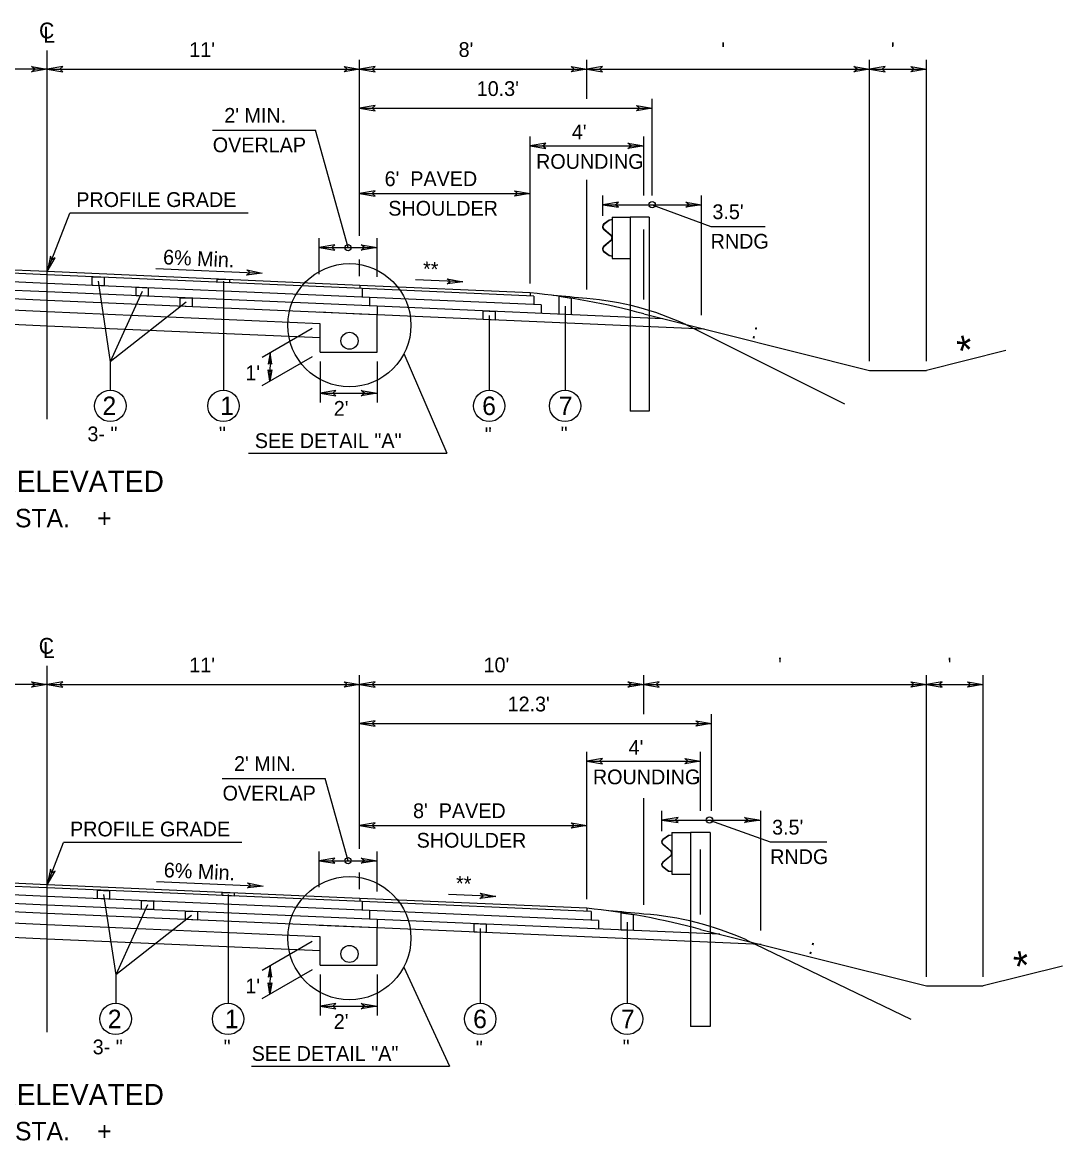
# Model space of a CAD drawing. Extents: x -592 to 1199, y -590 to 416.
# Drawn here: x 814.1 to 912.8, y 44 to 150 of the extents above; entities that cross this region are included whole.
import ezdxf

# ---------------------------------------------------------------- set-up
doc = ezdxf.new("R2010")
doc.units = 0
doc.layers.add('1', color=7, linetype='Continuous')
doc.layers.add('Des_ Drain_ Ftrs', color=7, linetype='Continuous')

msp = doc.modelspace()

# ---------------------------------------------------------------- linework, layer by layer
at = {"layer": '1'}
for p, q in [((816.45, 112.39), (816.45, 147.34)), ((846.08, 129.78), (846.08, 146.46)), ((867.64, 142.76), (867.64, 146.46)), ((894.46, 117.88), (894.46, 146.46)), ((899.85, 117.88), (899.85, 146.46)), ((816.45, 145.58), (786.81, 145.58)), ((816.45, 145.58), (846.08, 145.58)), ((846.08, 145.58), (867.64, 145.58)), ((867.64, 145.58), (894.46, 145.58)), ((894.46, 145.58), (899.85, 145.58)), ((873.83, 133.6), (873.83, 142.76)), ((846.08, 141.88), (873.83, 141.88)), ((832.11, 139.79), (841.88, 139.79)), ((844.98, 128.65), (841.88, 139.79)), ((862.25, 125.25), (862.25, 139.18)), ((873.03, 133.6), (873.03, 139.18)), ((862.25, 138.3), (873.03, 138.3)), ((867.64, 124.69), (867.64, 135.07)), ((846.08, 133.78), (862.25, 133.78)), ((869.14, 131.65), (869.14, 133.6)), ((869.14, 132.72), (878.52, 132.72)), ((873.83, 132.72), (879.39, 130.65)), ((878.52, 122.24), (878.52, 133.6)), ((816.45, 126.37), (818.59, 131.91)), ((835.5, 131.91), (818.59, 131.91)), ((870.05, 131.54), (870.05, 127.6)), ((870.05, 131.54), (871.74, 131.54)), ((871.74, 131.54), (871.74, 113.14)), ((873.56, 131.54), (871.74, 131.54)), ((873.56, 131.54), (873.56, 113.14)), ((869.74, 131.25), (869.22, 130.86)), ((869.22, 130.45), (869.95, 129.82)), ((869.75, 131.22), (869.24, 130.84)), ((870.05, 131.31), (869.74, 131.25)), ((870.05, 131.28), (869.75, 131.22)), ((879.39, 130.65), (884.54, 130.65)), ((842.24, 126.12), (842.24, 129.53)), ((847.73, 125.88), (847.73, 129.53)), ((869.2, 130.43), (869.94, 129.8)), ((870.02, 129.61), (870.02, 129.53)), ((870.05, 129.61), (870.05, 129.53)), ((873.03, 123.72), (873.03, 130.37)), ((842.24, 128.65), (847.73, 128.65)), ((869.94, 129.35), (869.2, 128.71)), ((869.95, 129.32), (869.22, 128.69)), ((816.45, 126.07), (786.47, 127.38)), ((816.45, 126.37), (786.81, 127.66)), ((846.08, 125.95), (846.08, 127.52)), ((869.22, 128.28), (869.74, 127.89)), ((869.24, 128.3), (869.75, 127.92)), ((869.74, 127.89), (870.05, 127.83)), ((869.75, 127.92), (870.05, 127.86)), ((870.05, 127.6), (871.74, 127.6)), ((816.45, 125.26), (785.55, 126.61)), ((846.09, 125.07), (816.45, 126.37)), ((826.74, 126.67), (836.85, 126.23)), ((816.45, 124.45), (784.62, 125.84)), ((846.32, 124.76), (816.45, 126.07)), ((847.03, 123.92), (816.45, 125.26)), ((821.27, 125.45), (822.43, 117.83)), ((833.16, 125.46), (833.16, 115.13)), ((855.86, 125.39), (851.37, 125.59)), ((816.45, 123.64), (784.62, 125.03)), ((847.73, 123.08), (816.45, 124.45)), ((825.45, 124.47), (822.43, 117.83)), ((862.25, 124.37), (846.09, 125.07)), ((846.09, 125.07), (846.09, 124.77)), ((862.61, 124.05), (846.32, 124.76)), ((846.32, 124.76), (846.32, 123.95)), ((862.25, 124.37), (862.25, 124.07)), ((816.45, 122.56), (790.01, 123.72)), ((847.73, 122.27), (816.45, 123.64)), ((829.62, 123.46), (822.43, 117.83)), ((863.31, 123.21), (847.03, 123.92)), ((847.03, 123.92), (847.03, 123.11)), ((847.73, 123.08), (847.73, 122.27)), ((874.86, 121.9), (847.73, 123.08)), ((862.61, 124.05), (862.61, 123.25)), ((863.31, 123.21), (863.31, 122.41)), ((865.57, 123.1), (865.57, 115.13)), ((869.14, 123.59), (869.14, 123.59)), ((816.45, 121.21), (790.01, 122.37)), ((842.34, 121.43), (816.45, 122.56)), ((846.08, 122.35), (842.25, 122.51)), ((847.73, 122.27), (846.09, 122.35)), ((847.73, 118.74), (847.73, 122.27)), ((878.78, 120.92), (847.73, 122.27)), ((858.37, 122.22), (858.37, 115.13)), ((873.03, 122.36), (894.46, 117)), ((842.34, 120.08), (816.45, 121.21)), ((841.58, 120.99), (836.82, 118.24)), ((842.34, 118.74), (842.34, 121.43)), ((842.34, 121.43), (842.34, 121.43)), ((877.02, 121.36), (892.07, 113.83)), ((907.38, 118.88), (899.85, 117)), ((822.43, 117.83), (822.43, 115.13)), ((841.58, 118.3), (836.81, 115.54)), ((837.59, 118.68), (837.57, 115.98)), ((842.34, 118.74), (847.73, 118.74)), ((842.34, 117.86), (842.34, 113.97)), ((847.73, 117.86), (847.73, 113.97)), ((850.29, 118.6), (854.34, 109.14)), ((894.46, 117), (899.85, 117)), ((842.34, 114.85), (847.73, 114.85)), ((873.56, 113.14), (871.74, 113.14)), ((835.55, 109.14), (854.34, 109.14)), ((816.45, 54.25), (816.45, 88.97)), ((846.08, 71.63), (846.08, 88.09)), ((873.03, 84.39), (873.03, 88.09)), ((899.85, 59.5), (899.85, 88.09)), ((905.24, 59.5), (905.24, 88.09)), ((816.45, 87.21), (786.81, 87.21)), ((816.45, 87.21), (846.08, 87.21)), ((846.08, 87.21), (873.03, 87.21)), ((873.03, 87.21), (899.85, 87.21)), ((899.85, 87.21), (905.24, 87.21)), ((879.45, 75.24), (879.45, 84.39)), ((846.08, 83.51), (879.45, 83.51)), ((867.64, 66.87), (867.64, 80.82)), ((878.41, 75.24), (878.41, 80.82)), ((867.64, 79.94), (878.41, 79.94)), ((833.04, 78.31), (842.81, 78.31)), ((844.98, 70.5), (842.81, 78.31)), ((873.03, 66.33), (873.03, 76.43)), ((874.76, 73.29), (874.76, 75.24)), ((874.76, 74.36), (884.15, 74.36)), ((879.28, 74.36), (885.04, 72.28)), ((884.15, 63.87), (884.15, 75.24)), ((846.08, 73.84), (867.64, 73.84)), ((816.45, 68.22), (817.99, 72.23)), ((834.91, 72.23), (817.99, 72.23)), ((875.38, 72.89), (874.85, 72.5)), ((875.39, 72.86), (874.86, 72.48)), ((875.71, 72.94), (875.38, 72.89)), ((875.71, 72.91), (875.39, 72.86)), ((875.71, 73.17), (875.71, 69.24)), ((875.71, 73.17), (877.46, 73.17)), ((877.46, 73.17), (877.46, 54.78)), ((879.35, 73.17), (877.46, 73.17)), ((879.35, 73.17), (879.35, 54.78)), ((885.04, 72.28), (890.39, 72.28)), ((842.24, 67.98), (842.24, 71.38)), ((847.73, 67.59), (847.73, 71.38)), ((874.83, 72.07), (875.59, 71.43)), ((874.85, 72.09), (875.61, 71.45)), ((875.68, 71.24), (875.68, 71.17)), ((875.71, 71.24), (875.71, 71.17)), ((878.41, 65.41), (878.41, 71.56)), ((842.24, 70.5), (847.73, 70.5)), ((875.59, 70.98), (874.83, 70.35)), ((875.61, 70.96), (874.85, 70.32)), ((816.45, 67.92), (786.47, 69.23)), ((816.45, 68.22), (786.81, 69.52)), ((846.08, 67.81), (846.08, 69.38)), ((874.85, 69.91), (875.38, 69.52)), ((874.86, 69.94), (875.39, 69.55)), ((875.38, 69.52), (875.71, 69.47)), ((875.39, 69.55), (875.71, 69.5)), ((875.71, 69.24), (877.46, 69.24)), ((816.45, 67.11), (785.55, 68.46)), ((846.09, 66.93), (816.45, 68.22)), ((846.32, 66.62), (816.45, 67.92)), ((826.81, 68.54), (836.92, 68.1)), ((816.45, 66.3), (784.62, 67.69)), ((816.45, 65.5), (784.62, 66.88)), ((847.03, 65.78), (816.45, 67.11)), ((821.78, 67.29), (822.94, 59.67)), ((833.6, 67.31), (833.6, 56.98)), ((867.64, 65.99), (846.09, 66.93)), ((846.09, 66.93), (846.09, 66.63)), ((859, 67.11), (854.5, 67.31)), ((847.73, 64.94), (816.45, 66.3)), ((825.95, 66.31), (822.94, 59.67)), ((868.04, 65.67), (846.32, 66.62)), ((846.32, 66.62), (846.32, 65.81)), ((868.73, 64.83), (847.03, 65.78)), ((847.03, 65.78), (847.03, 64.97)), ((867.64, 65.99), (867.64, 65.69)), ((816.45, 64.42), (790.01, 65.57)), ((847.73, 64.13), (816.45, 65.5)), ((830.13, 65.3), (822.94, 59.67)), ((847.73, 64.94), (847.73, 64.13)), ((880.25, 63.52), (847.73, 64.94)), ((868.04, 65.67), (868.04, 64.86)), ((868.73, 64.83), (868.73, 64.02)), ((874.76, 65.23), (874.76, 65.23)), ((816.45, 63.07), (790.01, 64.22)), ((842.34, 63.29), (816.45, 64.42)), ((846.08, 64.2), (842.25, 64.37)), ((847.73, 64.13), (846.09, 64.2)), ((847.73, 60.59), (847.73, 64.13)), ((884.17, 62.54), (847.73, 64.13)), ((857.52, 64.06), (857.52, 56.98)), ((871.46, 64.67), (871.46, 56.98)), ((878.41, 63.98), (899.85, 58.62)), ((842.34, 61.94), (816.45, 63.07)), ((841.58, 62.85), (836.82, 60.1)), ((842.34, 60.59), (842.34, 63.29)), ((842.34, 63.29), (842.34, 63.29)), ((882.76, 62.99), (898.38, 55.47)), ((837.59, 60.54), (837.57, 57.83)), ((842.34, 60.59), (847.73, 60.59)), ((912.77, 60.5), (905.24, 58.62)), ((822.94, 59.67), (822.94, 56.98)), ((841.58, 60.15), (836.81, 57.4)), ((842.34, 59.71), (842.34, 55.83)), ((847.73, 59.71), (847.73, 55.83)), ((850.26, 60.41), (854.62, 51.02)), ((899.85, 58.62), (905.24, 58.62)), ((842.34, 56.71), (847.73, 56.71)), ((879.35, 54.78), (877.46, 54.78)), ((835.83, 51.02), (854.62, 51.02))]:
    msp.add_line(p, q, dxfattribs=at)
for points in [[(820.7, 125.88), (821.84, 125.83), (821.84, 125.02), (820.7, 125.07)], [(832.58, 125.66), (833.73, 125.61), (833.73, 125.31), (832.58, 125.36)], [(824.87, 124.89), (826.02, 124.84), (826.02, 124.03), (824.87, 124.08)], [(829.05, 123.9), (830.19, 123.85), (830.19, 123.04), (829.05, 123.09)], [(865, 124.03), (866.14, 123.85), (866.14, 122.28), (865, 122.33)], [(857.8, 122.64), (858.95, 122.59), (858.95, 121.78), (857.8, 121.83)], [(821.2, 67.71), (822.35, 67.66), (822.35, 66.86), (821.2, 66.91)], [(833.03, 67.5), (834.18, 67.45), (834.18, 67.15), (833.03, 67.2)], [(825.38, 66.72), (826.53, 66.67), (826.53, 65.86), (825.38, 65.91)], [(830.7, 65.68), (830.7, 64.87), (829.55, 64.92), (829.55, 65.73)], [(870.88, 65.57), (872.03, 65.39), (872.03, 63.88), (870.88, 63.93)], [(856.95, 64.54), (858.09, 64.49), (858.09, 63.68), (856.95, 63.73)]]:
    msp.add_lwpolyline(points, close=True, dxfattribs=at)
for centre, radius in [((873.83, 132.72), 0.3), ((844.98, 128.65), 0.3), ((845.11, 121.29), 5.84), ((845.12, 119.81), 0.808), ((822.43, 113.64), 1.49), ((833.16, 113.64), 1.49), ((858.37, 113.64), 1.49), ((865.57, 113.64), 1.49), ((844.98, 70.5), 0.3), ((845.11, 63.15), 5.84), ((845.12, 61.66), 0.808), ((822.94, 55.5), 1.49), ((833.6, 55.5), 1.49), ((857.52, 55.5), 1.49), ((871.46, 55.5), 1.49)]:
    msp.add_circle(centre, radius, dxfattribs=at)
for centre, radius, start, end in [((869.39, 130.64), 0.278, 126.9799, 229.021), ((869.39, 130.64), 0.249, 126.9799, 229.021), ((869.77, 129.61), 0.249, 0, 49.0365), ((869.77, 129.53), 0.249, 310.9635, 0), ((869.77, 129.61), 0.278, 0, 49.0365), ((869.77, 129.53), 0.278, 310.9635, 0), ((869.39, 128.5), 0.278, 130.979, 233.0201), ((869.39, 128.5), 0.249, 130.979, 233.0201), ((855.37, 57.53), 67.19, 74.7602, 84.1188), ((856.81, 23.15), 101.24, 83.8633, 85.6775), ((865.51, 96.52), 27.37, 65.1374, 85.5513), ((860.75, -0.85), 67.19, 74.7602, 84.1188)]:
    msp.add_arc(centre, radius, start, end, dxfattribs=at)
msp.add_ellipse((879.28, 74.36), major_axis=(-0.311, 0), ratio=0.964041, dxfattribs=at)
for centre, major_axis, start_param, end_param in [((875.02, 72.28), (-0.288, 0), 5.35781, 7.138763), ((875.02, 72.28), (-0.258, 0), 5.35781, 7.138763), ((875.42, 71.24), (0.258, 0), 0, 0.855848), ((875.42, 71.17), (0.258, 0), 5.427337, 6.283185), ((875.42, 71.24), (0.288, 0), 0, 0.855848), ((875.42, 71.17), (0.288, 0), 5.427337, 6.283185), ((875.02, 70.14), (-0.288, 0), 5.427608, 7.208561), ((875.02, 70.14), (-0.258, 0), 5.427608, 7.208561), ((861.8, -35.22), (105.02, 0), 1.463691, 1.495354), ((870.83, 38.16), (28.39, 0), 1.136862, 1.493152)]:
    msp.add_ellipse(centre, major_axis=major_axis, ratio=0.964041, start_param=start_param, end_param=end_param, dxfattribs=at)
at = {"layer": 'Des_ Drain_ Ftrs'}
for points in [[(816.45, 145.58), (814.96, 145.33), (815.26, 145.58), (814.96, 145.83)], [(816.45, 145.58), (817.94, 145.33), (817.64, 145.58), (817.94, 145.83)], [(846.08, 145.58), (844.6, 145.33), (844.89, 145.58), (844.6, 145.83)], [(846.08, 145.58), (847.57, 145.33), (847.28, 145.58), (847.57, 145.83)], [(867.64, 145.58), (866.15, 145.33), (866.44, 145.58), (866.15, 145.83)], [(867.64, 145.58), (869.13, 145.33), (868.83, 145.58), (869.13, 145.83)], [(894.46, 145.58), (892.97, 145.33), (893.27, 145.58), (892.97, 145.83)], [(894.46, 145.58), (895.95, 145.33), (895.65, 145.58), (895.95, 145.83)], [(899.85, 145.58), (898.36, 145.33), (898.66, 145.58), (898.36, 145.83)], [(846.08, 141.88), (847.57, 141.63), (847.27, 141.88), (847.57, 142.12)], [(873.83, 141.88), (872.34, 141.63), (872.64, 141.88), (872.34, 142.12)], [(862.25, 138.3), (863.74, 138.05), (863.44, 138.3), (863.74, 138.55)], [(873.03, 138.3), (871.54, 138.05), (871.83, 138.3), (871.54, 138.55)], [(846.08, 133.78), (847.57, 133.53), (847.28, 133.78), (847.57, 134.03)], [(862.25, 133.78), (860.76, 133.53), (861.06, 133.78), (860.76, 134.03)], [(869.14, 132.72), (870.63, 132.47), (870.33, 132.72), (870.63, 132.97)], [(878.52, 132.72), (877.03, 132.47), (877.33, 132.72), (877.03, 132.97)], [(842.24, 128.65), (843.73, 128.4), (843.43, 128.65), (843.73, 128.9)], [(847.73, 128.65), (846.24, 128.4), (846.53, 128.65), (846.24, 128.9)], [(816.45, 126.37), (817.21, 127.67), (816.88, 127.48), (816.75, 127.85)], [(836.85, 126.23), (835.35, 126.05), (835.66, 126.28), (835.38, 126.54)], [(855.86, 125.39), (854.37, 125.21), (854.67, 125.44), (854.39, 125.7)], [(837.59, 118.68), (837.4, 117.6), (837.58, 117.81), (837.76, 117.6)], [(837.57, 115.98), (837.39, 117.06), (837.57, 116.85), (837.75, 117.06)], [(842.34, 114.85), (843.83, 114.6), (843.54, 114.85), (843.83, 115.1)], [(847.73, 114.85), (846.24, 114.6), (846.54, 114.85), (846.24, 115.1)], [(816.45, 87.21), (814.96, 86.97), (815.26, 87.21), (814.96, 87.46)], [(816.45, 87.21), (817.94, 86.97), (817.64, 87.21), (817.94, 87.46)], [(846.08, 87.21), (844.6, 86.97), (844.89, 87.21), (844.6, 87.46)], [(846.08, 87.21), (847.57, 86.97), (847.28, 87.21), (847.57, 87.46)], [(873.03, 87.21), (871.54, 86.97), (871.83, 87.21), (871.54, 87.46)], [(873.03, 87.21), (874.51, 86.97), (874.22, 87.21), (874.51, 87.46)], [(899.85, 87.21), (898.36, 86.97), (898.66, 87.21), (898.36, 87.46)], [(899.85, 87.21), (901.34, 86.97), (901.04, 87.21), (901.34, 87.46)], [(905.24, 87.21), (903.75, 86.97), (904.04, 87.21), (903.75, 87.46)], [(846.08, 83.51), (847.57, 83.26), (847.28, 83.51), (847.57, 83.76)], [(879.45, 83.51), (877.96, 83.26), (878.26, 83.51), (877.96, 83.76)], [(867.64, 79.94), (869.13, 79.69), (868.83, 79.94), (869.13, 80.19)], [(878.41, 79.94), (876.93, 79.69), (877.22, 79.94), (876.93, 80.19)], [(874.76, 74.36), (876.31, 74.11), (876, 74.36), (876.31, 74.6)], [(884.15, 74.36), (882.6, 74.11), (882.91, 74.36), (882.6, 74.6)], [(846.08, 73.84), (847.57, 73.59), (847.28, 73.84), (847.57, 74.09)], [(867.64, 73.84), (866.15, 73.59), (866.44, 73.84), (866.15, 74.09)], [(842.24, 70.5), (843.73, 70.26), (843.43, 70.5), (843.73, 70.75)], [(847.73, 70.5), (846.24, 70.26), (846.53, 70.5), (846.24, 70.75)], [(816.45, 68.22), (817.21, 69.52), (816.88, 69.34), (816.75, 69.7)], [(836.92, 68.1), (835.43, 67.92), (835.73, 68.15), (835.45, 68.41)], [(859, 67.11), (857.5, 66.93), (857.8, 67.16), (857.52, 67.42)], [(837.59, 60.54), (837.4, 59.46), (837.58, 59.67), (837.76, 59.45)], [(837.57, 57.83), (837.39, 58.92), (837.57, 58.7), (837.75, 58.92)], [(842.34, 56.71), (843.83, 56.46), (843.54, 56.71), (843.83, 56.95)], [(847.73, 56.71), (846.24, 56.46), (846.54, 56.71), (846.24, 56.95)]]:
    msp.add_lwpolyline(points, close=True, dxfattribs=at)

# ---------------------------------------------------------------- texts
at = {"layer": '1'}
for s, height, p in [("11'", 1.4, (829.92, 146.73)), ("8'", 1.4, (855.47, 146.73)), ("  '", 1.4, (879.35, 146.73)), (" '", 1.4, (895.96, 146.73)), ("10.3'", 1.4, (857.19, 143.03)), ("2' MIN.", 1.4, (833.24, 140.49)), ("4'", 1.4, (866.21, 138.92)), ('OVERLAP', 1.4, (832.15, 137.69)), ('ROUNDING', 1.4, (862.82, 136.12)), ("6'  PAVED", 1.4, (848.45, 134.48)), ('PROFILE GRADE', 1.4, (819.2, 132.5)), ('SHOULDER', 1.4, (848.8, 131.68)), ("3.5'", 1.4, (879.55, 131.35)), ('RNDG', 1.4, (879.38, 128.55)), ('2', 1.75, (821.69, 112.77)), ('6', 1.75, (857.71, 112.77)), ('1', 1.75, (832.85, 112.77)), ("2'", 1.4, (843.63, 112.7)), ('7', 1.75, (864.98, 112.77)), ('3- "', 1.4, (820.26, 110.28)), (' "', 1.4, (832.21, 110.28)), (' "', 1.4, (857.43, 110.19)), (' "', 1.4, (864.63, 110.28)), ('SEE DETAIL "A"', 1.4, (836.14, 109.64)), ('SUPERELEVATED', 2, (804.33, 105.48)), ('STA.    +      TO STA.    +     ', 1.75, (796.42, 102.12)), ("11'", 1.4, (829.92, 88.37)), ("10'", 1.4, (857.84, 88.37)), ("  '", 1.4, (884.74, 88.37)), (" '", 1.4, (901.35, 88.37)), ("12.3'", 1.4, (860.12, 84.66)), ("4'", 1.4, (871.6, 80.55)), ("2' MIN.", 1.4, (834.17, 79.01)), ('ROUNDING', 1.4, (868.21, 77.75)), ('OVERLAP', 1.4, (833.08, 76.21)), ("8'  PAVED", 1.4, (851.15, 74.54)), ("3.5'", 1.4, (885.21, 72.98)), ('PROFILE GRADE', 1.4, (818.61, 72.81)), ('SHOULDER', 1.4, (851.49, 71.74)), ('RNDG', 1.4, (885.03, 70.18)), ('2', 1.75, (822.19, 54.62)), ('1', 1.75, (833.3, 54.62)), ('6', 1.75, (856.85, 54.62)), ('7', 1.75, (870.87, 54.62)), ("2'", 1.4, (843.63, 54.55)), ('3- "', 1.4, (820.76, 52.14)), (' "', 1.4, (832.66, 52.14)), (' "', 1.4, (856.58, 52.04)), (' "', 1.4, (870.51, 52.14)), ('SEE DETAIL "A"', 1.4, (835.84, 51.52)), ('SUPERELEVATED', 2, (804.33, 47.33)), ('STA.    +      TO STA.    +     ', 1.75, (796.42, 43.98))]:
    msp.add_text(s, height=height, dxfattribs=at).set_placement(p)
for s, height, rotation, p in [('6% Min.', 1.4, 357.3732, (827.41, 127.07)), ('**', 1.4, 357.2161, (852.05, 125.95)), (' : ', 1.4, 345.7718, (882.69, 120.23)), ('*', 2.8, 12.8479, (903.16, 117.4)), ("1'", 1.4, 0.1438, (835.24, 116.07)), ('6% Min.', 1.4, 357.3731, (827.48, 68.94)), ('**', 1.4, 357.216, (855.18, 67.67)), (' : ', 1.4, 345.7718, (888.08, 61.85)), ('*', 2.8, 12.8479, (908.55, 59.02)), ("1'", 1.4, 0.1438, (835.24, 57.92))]:
    msp.add_text(s, height=height, rotation=rotation, dxfattribs=at).set_placement(p)
at = {"layer": 'Des_ Drain_ Ftrs'}
for s, p in [('C', (815.67, 148.49)), ('L', (816.06, 148.09)), ('C', (815.64, 90.13)), ('L', (816.03, 89.73))]:
    msp.add_text(s, height=1.5, dxfattribs=at).set_placement(p)

doc.saveas('drawing.dxf')
